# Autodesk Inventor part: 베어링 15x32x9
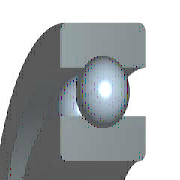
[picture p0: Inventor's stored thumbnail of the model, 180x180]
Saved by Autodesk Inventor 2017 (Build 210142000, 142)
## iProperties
IsCustomPart: 0
Created: 2012-02
Part Number: 베어링 15x32x9
Material: 강철, 연강
Description: 깊은 그루브 볼 베어링
Document SubType Name: Modeling
Standard: KS B 2023
Designer: mduedu
Standards Organization: KS
Language: ko-KR
Size Designation: 6002 - 15 x 32 x 9
Categories: <MemberInstance><Categories><Category DisplayName="샤프트 부품" InternalName="7f7aeb1f-a693-4053-b835-cee3144e0d98" Mnemonic="SHFT"><Category DisplayName="베어링" Inter
Density: 1 g/cm^3
Appearance: 노란색
Author: mduedu
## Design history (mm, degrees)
sketch "스케치" dims "d0" = 4.42 (= -0.26 x WD + 0.26 x BD)
  geometry: L1 (2.29, 11.75)-(6.71, 11.75); L2 (4.5, 11.75)-(4.5, 9.54); L3 (4.5, 11.75)-(4.5, 13.96); L4 (2.858, 10.271)-(0, 10.271); L5 (0, 7.5)-(9, 7.5); L6 (2.858, 13.229)-(0, 13.229); L7 (0, 16)-(9, 16); L8 (9, 7.5)-(9, 10.271); L9 (6.142, 10.271)-(9, 10.271); L10 (6.142, 13.229)-(9, 13.229); L11 (9, 16)-(9, 13.229); L12 (-1.4, 0)-(8.4, 0) reference; L13 (0, -0.3)-(0, 5.3) reference
  constraints: 22 end point, 4 point on line, 2 collinear, 2 perpendicular, 2 symmetric about line, 1 midpoint, 1 parallel, 14 other
  dimensions: "d9" = 15 diameter of L5 L12 (= WD); "d11" = 32 diameter of L7 L12 (= BD); "d12" = 9 distance between parallel lines of L8 L13 (= KB); "d13" = 20.542 diameter of L9 L12 (= 0.326 x BD + 0.674 x WD)
revolve "본체" stored, may be unused: angle "d6" = 90 deg
revolve "볼" stored, may be unused: angle "d7" = 90 deg
pattern_circular "IDS_ARRAYBALL[SIMPL:T]" dims angle "d3" = 360 deg
body "Solid1"
fillet "모깎기1" dims "d1" = 0.3 (= KRS)
other parameters: "WD" = 15 [user parameter; used in 5 equation terms], "BD" = 32 [user parameter; used in 5 equation terms], "KB" = 9 [user parameter; used in 1 equation term], "KRS" = 0.3 [user parameter; used in 1 equation term], "d4" = 0, "d5" = 0, "d8" = 0, "d14" = 0, "d15" = 0, "BBA" = 0 [user parameter], "BC0" = 2850000 [user parameter], "BC" = 5590000 [user parameter], "BR" = 16 (= 0.5 x BD) [user parameter], "WR" = 7.5 (= 0.5 x WD) [user parameter]
